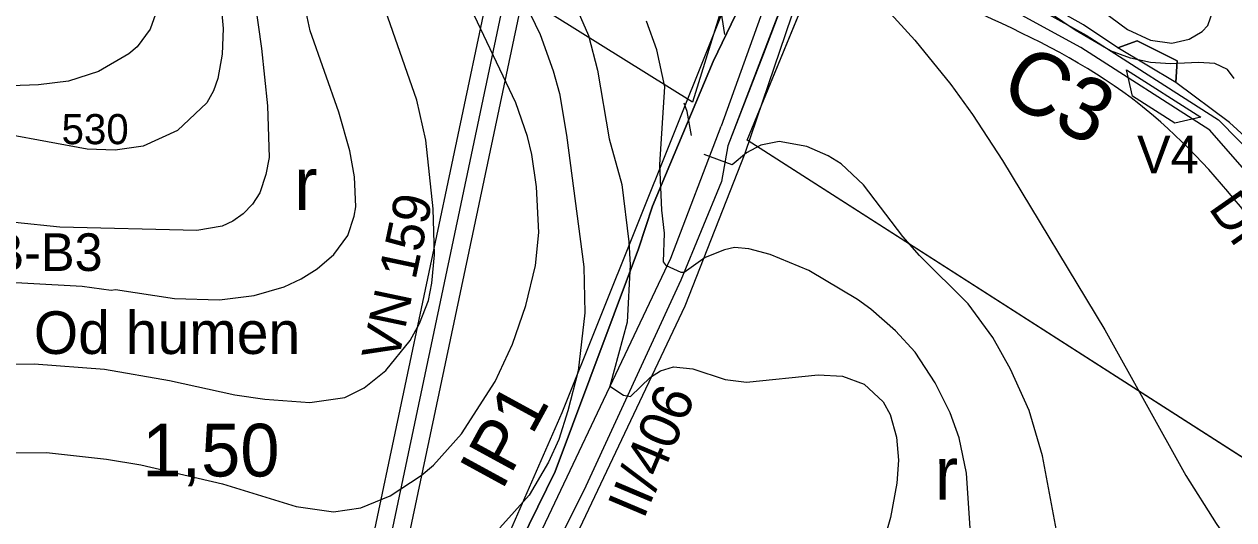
# Model space of a CAD drawing. Extents: x -684583 to -680383, y -1157874 to -1154904.
# Drawn here: x -683060.3 to -682578.4, y -1156304.8 to -1156107.3 of the extents above; entities that cross this region are included whole.
import ezdxf

# ---------------------------------------------------------------- set-up
doc = ezdxf.new("R2010")
doc.units = 0
for name, color, linetype in [('01_DOPRAVA', 7, 'Continuous'), ('01_MÍSTNÍ_NÁZVY', 7, 'Continuous'), ('01_VRSTEVNICE', 7, 'Continuous'), ('02_KULTURY STAV', 7, 'Continuous'), ('03_PC_NÁVRH', 7, 'Continuous'), ('03_PC_OBJEKTY_NÁVRH', 7, 'Continuous'), ('03_PC_POPIS_NÁVRH', 7, 'Continuous'), ('05_VHO_MELIORACE', 7, 'Continuous'), ('06_BIOGEOGRAFIE', 7, 'Continuous'), ('06_ÚSES_IP', 7, 'Continuous'), ('07_ELEKTRO', 7, 'Continuous'), ('07_OCH_P A POPISY TI', 7, 'Continuous')]:
    doc.layers.add(name, color=color, linetype=linetype)

msp = doc.modelspace()

# ---------------------------------------------------------------- linework, layer by layer
at = {"layer": '01_DOPRAVA'}
for points in [[(-682444.78, -1155001.44), (-682484.97, -1155081.41), (-682523.81, -1155212.27), (-682554.69, -1155333.36), (-682575.58, -1155465.36), (-682603.29, -1155587.36), (-682620.55, -1155650.97), (-682668.34, -1155796.22), (-682702.3, -1155906.34), (-682764.53, -1156097.63), (-682782.62, -1156147.93)], [(-683054.51, -1157758.92), (-683045.66, -1157702.14), (-683033.32, -1157625.99), (-683033.32, -1157571.3), (-683045.07, -1157508.09), (-683105.62, -1157372.25), (-683148.82, -1157294.04), (-683163.81, -1157254.05), (-683168.81, -1157196.71), (-683165.28, -1157159.67), (-683135.89, -1157075.28), (-683079.46, -1156981.49), (-683035.96, -1156902.98), (-682993.94, -1156817.72), (-682972.78, -1156716.87), (-682952.5, -1156631.31), (-682921.05, -1156497.23), (-682883.43, -1156372.57), (-682870.79, -1156344.34), (-682802.61, -1156200.56), (-682782.62, -1156147.93)]]:
    msp.add_lwpolyline(points, dxfattribs=at)
at = {"layer": '01_VRSTEVNICE'}
for points in [[(-683067.75, -1155919.88), (-683036.22, -1155954.68), (-683024.67, -1155968.38), (-683001.7, -1155998.33), (-682988.3, -1156021.15), (-682981.45, -1156037.13), (-682975.74, -1156055.39), (-682971.18, -1156078.21), (-682965.76, -1156117.01), (-682963.33, -1156139.83), (-682962.76, -1156160.37), (-682964.05, -1156167.22), (-682966.47, -1156174.5), (-682969.33, -1156179.06), (-682973.03, -1156182.91), (-682977.17, -1156185.76), (-682981.45, -1156187.76), (-682991.58, -1156189.47), (-683046.07, -1156188.19), (-683064.04, -1156186.33)], [(-683080.59, -1155932.71), (-683049.06, -1155970.51), (-683014.69, -1156013.74), (-683007.84, -1156023.44), (-683002.13, -1156033.14), (-682993.15, -1156052.53), (-682987.01, -1156073.08), (-682982.02, -1156098.75), (-682981.02, -1156109.02), (-682981.45, -1156119.29), (-682983.16, -1156128.99), (-682984.87, -1156133.84), (-682987.58, -1156138.69), (-682999.28, -1156149.68), (-683012.97, -1156155.95), (-683024.1, -1156157.52), (-683035.23, -1156157.09), (-683066.89, -1156151.24)], [(-683077.45, -1155954.68), (-683041.5, -1156006.32), (-683034.8, -1156016.87), (-683026.24, -1156032.85), (-683022.96, -1156040.84), (-683021.39, -1156047.54), (-683010.41, -1156079.07), (-683007.41, -1156092.76), (-683007.98, -1156103.32), (-683010.12, -1156109.31), (-683015.26, -1156116.3), (-683018.68, -1156119.15), (-683030.66, -1156126.14), (-683042.65, -1156129.99), (-683054.63, -1156131.42), (-683087.43, -1156132.7)], [(-682860.35, -1155997.05), (-682824.68, -1156034.56), (-682803, -1156061.09), (-682796.3, -1156070.51), (-682791.31, -1156079.07), (-682786.17, -1156090.48), (-682783.03, -1156100.46), (-682781.32, -1156111.45)], [(-682881.82, -1156065.53), (-682873.04, -1156078.5), (-682860.77, -1156099.04), (-682854.78, -1156111.45), (-682849.5, -1156125.85), (-682847.08, -1156134.98), (-682844.23, -1156151.53), (-682837.38, -1156204.02), (-682836.95, -1156222.28), (-682839.66, -1156245.39), (-682843.66, -1156261.37), (-682847.36, -1156272.78), (-682851.36, -1156281.91), (-682859.06, -1156295.03), (-682870.76, -1156308.01)], [(-683082.01, -1156243.11), (-683056.34, -1156242.68), (-683028.38, -1156244.82), (-683002.42, -1156249.24), (-682976.46, -1156254.95), (-682964.48, -1156256.8), (-682946.5, -1156258.08), (-682932.52, -1156256.09), (-682924.82, -1156252.24), (-682916.26, -1156245.25), (-682906.56, -1156233.41), (-682902.85, -1156226.56), (-682899.29, -1156217.43), (-682897.86, -1156210.58), (-682896.86, -1156199.17), (-682897.43, -1156180.91), (-682900.29, -1156153.53), (-682903.85, -1156137.55), (-682922.97, -1156082.78)], [(-682578.2, -1156128.99), (-682580.91, -1156125.43), (-682585.9, -1156123), (-682592.46, -1156122.57), (-682603.59, -1156123.14), (-682611.58, -1156122.57), (-682619.56, -1156120.86), (-682627.55, -1156117.87), (-682641.53, -1156109.73), (-682680.9, -1156083.06)], [(-683078.31, -1156209.44), (-683037.22, -1156211.73), (-683025.67, -1156213.29), (-683023.96, -1156213.01), (-683000.42, -1156216.57), (-682982.45, -1156217.15), (-682968.75, -1156215.43), (-682956.77, -1156212.01), (-682949.93, -1156208.73), (-682943.65, -1156204.74), (-682936.95, -1156199.03), (-682931.38, -1156191.47), (-682928.81, -1156183.77), (-682928.24, -1156180.06), (-682928.67, -1156168.08), (-682930.53, -1156157.81), (-682934.95, -1156142.4), (-682946.36, -1156110.02), (-682949.93, -1156093.05)], [(-682745.52, -1156093.9), (-682737.96, -1156090.76), (-682731.82, -1156090.48), (-682727.69, -1156091.9), (-682722.12, -1156095.33), (-682705.43, -1156113.73), (-682691.17, -1156131.28), (-682682.47, -1156143.26), (-682670.49, -1156161.66), (-682629.69, -1156229.13), (-682597.45, -1156287.18), (-682585.33, -1156306.3), (-682572.83, -1156324.37)], [(-682841.52, -1156098.18), (-682835.53, -1156111.88), (-682831.96, -1156125.57), (-682827.25, -1156152.96), (-682822.26, -1156171.21), (-682819.41, -1156194.04), (-682818.84, -1156203.17), (-682820.12, -1156225.99), (-682826.97, -1156251.52), (-682821.55, -1156255.09), (-682818.69, -1156255.66), (-682810.71, -1156247.96), (-682806.85, -1156245.39), (-682801.58, -1156243.82), (-682793.87, -1156244.68), (-682781.04, -1156248.96), (-682772.48, -1156249.95), (-682743.95, -1156247.1), (-682734.25, -1156247.53), (-682725.69, -1156250.81), (-682718.13, -1156257.8), (-682715.28, -1156262.79), (-682712.71, -1156271.92), (-682712, -1156281.05), (-682712.57, -1156290.18), (-682715.13, -1156303.87), (-682721.7, -1156326.7)], [(-682637.11, -1156097.18), (-682620.7, -1156109.45), (-682611.58, -1156113.73), (-682603.02, -1156114.87), (-682596.17, -1156113.3), (-682591.03, -1156110.16), (-682588.75, -1156107.88), (-682586.75, -1156102.17)], [(-683087.72, -1156278.2), (-683051.49, -1156278.05), (-683027.52, -1156280.62), (-683013.83, -1156282.9), (-682981.31, -1156290.46), (-682951.92, -1156299.45), (-682937.09, -1156301.59), (-682926.25, -1156300.02), (-682914.55, -1156295.31), (-682902.14, -1156287.18), (-682897.29, -1156283.05), (-682886.02, -1156270.49), (-682872.61, -1156249.67), (-682865.77, -1156234.83), (-682860.49, -1156219.43), (-682856.64, -1156203.45), (-682855.21, -1156190.33), (-682856.21, -1156172.07), (-682858.06, -1156159.23), (-682859.78, -1156152.1), (-682864.48, -1156138.69), (-682881.03, -1156103.74)], [(-682683.18, -1156312.15), (-682684.89, -1156286.19), (-682687.75, -1156272.21), (-682691.31, -1156262.22), (-682697.3, -1156250.24), (-682705.29, -1156237.97), (-682713.14, -1156229.56), (-682722.98, -1156220.85), (-682728.26, -1156217), (-682747.66, -1156205.45), (-682763.06, -1156199.03), (-682771.62, -1156196.89), (-682777.33, -1156196.32), (-682781.32, -1156197.18), (-682789.02, -1156200.31), (-682797.3, -1156206.3), (-682798.58, -1156206.3), (-682804.43, -1156203.59), (-682805.57, -1156202.03), (-682805.14, -1156190.61), (-682806.28, -1156181.49), (-682807, -1156163.23), (-682805, -1156132.27), (-682808.28, -1156117.58), (-682812.42, -1156106.17)], [(-682794.44, -1156151.67), (-682796.16, -1156142.12), (-682797.3, -1156138.83)], [(-682600.59, -1156391.28), (-682610.86, -1156379.33), (-682622.13, -1156364.93), (-682631.54, -1156351.23), (-682639.25, -1156337.25), (-682643.67, -1156327.27), (-682648.23, -1156313.29), (-682654.65, -1156279.34), (-682659.93, -1156261.22), (-682667.35, -1156244.82), (-682674.34, -1156232.12), (-682684.18, -1156218.72), (-682703.58, -1156199.46), (-682710.28, -1156191.9), (-682725.97, -1156171.36), (-682734.82, -1156162.94), (-682739.95, -1156159.8), (-682748.51, -1156156.09), (-682759.5, -1156154.1), (-682766.77, -1156155.52), (-682772.48, -1156158.52), (-682778.18, -1156163.37), (-682789.45, -1156159.23)]]:
    msp.add_lwpolyline(points, dxfattribs=at)
at = {"layer": '02_KULTURY STAV'}
for points in [[(-682866.04, -1156320.76), (-682848.78, -1156285.62), (-682834.97, -1156248.66), (-682815.59, -1156196.79), (-682810.04, -1156179.89), (-682785.78, -1156122.22), (-682776.79, -1156103.44), (-682762.11, -1156061.38), (-682758.74, -1156052.65), (-682753.41, -1156039.97), (-682742.95, -1156008.33), (-682725.67, -1156001.43), (-682739.11, -1156046.65), (-682740.04, -1156050.18), (-682744.64, -1156063.3), (-682765.72, -1156119.15), (-682779.93, -1156155.81), (-682782.44, -1156169.94), (-682798.74, -1156209.36), (-682837.34, -1156293.13), (-682860.97, -1156340.11)], [(-682569.3, -1156156.35), (-682580.04, -1156146.44), (-682601.47, -1156130.49), (-682600.97, -1156121.96), (-682616.85, -1156113.92), (-682624.62, -1156116.74), (-682638.27, -1156107.54), (-682659.05, -1156095.72), (-682693.74, -1156078.06), (-682714.33, -1156069.98), (-682731.17, -1156065.1), (-682744.64, -1156063.3), (-682742.82, -1156058.77), (-682735.27, -1156055.51), (-682726.38, -1156048.39), (-682702.07, -1156019.82), (-682695.09, -1156023.72), (-682560.35, -1156103.1)], [(-682596.72, -1156380.07), (-682557.32, -1156288.22), (-682537.57, -1156239.43), (-682529.35, -1156221.47), (-682529.35, -1156221.47), (-682525.25, -1156214.91), (-682536.68, -1156197.77), (-682569.3, -1156156.35), (-682580.04, -1156146.44), (-682601.47, -1156130.49), (-682624.62, -1156116.74), (-682638.27, -1156107.54), (-682659.05, -1156095.72), (-682693.74, -1156078.06), (-682714.33, -1156069.98), (-682731.17, -1156065.1), (-682740.76, -1156063.41), (-682744.64, -1156063.3), (-682779.93, -1156155.81), (-682782.44, -1156169.94), (-682798.74, -1156209.36), (-682837.34, -1156293.13), (-682860.97, -1156340.11)], [(-682776.79, -1156103.44), (-682785.78, -1156122.22), (-682810.04, -1156179.89), (-682815.59, -1156196.79), (-682834.97, -1156248.66), (-682848.78, -1156285.62), (-682866.04, -1156320.76)]]:
    msp.add_lwpolyline(points, dxfattribs=at)
msp.add_lwpolyline([(-682624.62, -1156116.74), (-682616.85, -1156113.92), (-682600.97, -1156121.96), (-682601.47, -1156130.49)], close=True, dxfattribs=at)
at = {"layer": '03_PC_NÁVRH'}
msp.add_lwpolyline([(-682748.06, -1156060.15), (-682693.66, -1156080.3), (-682637.14, -1156111.72), (-682584.4, -1156145.39), (-682568.41, -1156161.75), (-682527.4, -1156217.35)], dxfattribs=at)
at = {"layer": '03_PC_OBJEKTY_NÁVRH'}
msp.add_lwpolyline([(-682540.56, -1156208.64), (-682574.04, -1156165.3), (-682587.85, -1156149.61), (-682639.37, -1156116.57), (-682695.33, -1156085.89), (-682737, -1156069.49)], dxfattribs=at)
msp.add_lwpolyline([(-682591.44, -1156144.41), (-682601.8, -1156146.7), (-682618.66, -1156135.94), (-682621.16, -1156125.44)], close=True, dxfattribs=at)
at = {"layer": '05_VHO_MELIORACE'}
for p, q in [((-682772.31, -1156153.49), (-682747.8, -1156093.97)), ((-682567.04, -1156285.02), (-682772.31, -1156153.49))]:
    msp.add_line(p, q, dxfattribs=at)
msp.add_lwpolyline([(-682427.32, -1155652.04), (-682442.64, -1155733.79), (-682379.89, -1155766.86), (-682399.94, -1155848.22), (-682465.23, -1155827.02), (-682513.91, -1155819), (-682556.29, -1155928.43), (-682568.9, -1156017.02), (-682570.04, -1156062.28), (-682551.72, -1156093.79), (-682504.18, -1156161.97), (-682541.38, -1156231.07), (-682567.04, -1156285.02), (-682772.31, -1156153.49), (-682747.8, -1156093.97), (-682704.39, -1155977.74), (-682664.8, -1155838.52), (-682635.04, -1155749.47), (-682580.41, -1155551.03)], dxfattribs=at)
msp.add_lwpolyline([(-683016.49, -1155781.73), (-682936.04, -1155794.17), (-682848.83, -1155761.96), (-682691.86, -1155808.93), (-682793.99, -1156138.37), (-682858.18, -1156098.46), (-682817.93, -1155910.57), (-682879.64, -1155866.28), (-683019.17, -1155809.91)], close=True, dxfattribs=at)
at = {"layer": '06_BIOGEOGRAFIE'}
for points in [[(-682624.87, -1154935.44), (-682669.05, -1155140.04), (-682739.65, -1155253.72), (-682834.36, -1155382.91), (-682941.12, -1155661.96), (-683008.28, -1155760.14), (-683056.49, -1155810.09), (-683084.04, -1155808.37), (-683154.45, -1155886.49), (-683231.94, -1156062.19), (-683280.08, -1156211.64), (-683362.74, -1156430.39), (-683497.05, -1156731.83), (-683541.82, -1156781.78), (-683638.25, -1156792.12), (-683701.96, -1156768), (-683817.33, -1156693.94)], [(-682538.3, -1156231.46), (-682619.23, -1156136.72), (-682741.49, -1156072.99), (-682905.07, -1155940.36), (-683017, -1155857.68), (-683037.66, -1155826.67), (-683017, -1155811.17), (-682820.7, -1155868.01), (-682758.71, -1155893.85), (-682674.33, -1155943.8), (-682548.63, -1156054.04), (-682459.09, -1156176.34)]]:
    msp.add_spline(points, degree=3, dxfattribs=at)
at = {"layer": '06_ÚSES_IP'}
for points in [[(-682530.18, -1155187.74), (-682556.31, -1155287.32), (-682580.65, -1155417.4), (-682596.62, -1155505.37), (-682619.02, -1155596.96), (-682637.3, -1155662.36), (-682672.55, -1155772.07), (-682712.43, -1155905.02), (-682772.45, -1156078.06), (-682846.1, -1156262.2), (-682899.06, -1156383.28), (-682928.82, -1156472.07), (-682968.71, -1156622.54), (-683017.6, -1156838.34)], [(-683045.5, -1156945.1), (-682993.87, -1156850.83), (-682970.35, -1156763.63), (-682943.14, -1156635.49), (-682907.69, -1156485.87), (-682877.43, -1156403.71), (-682855.81, -1156343.74), (-682797.01, -1156219.49), (-682773.09, -1156158.67), (-682722.07, -1156008.47), (-682663.84, -1155833.77), (-682598.99, -1155629.09), (-682554.6, -1155429.31), (-682533.56, -1155299)]]:
    msp.add_lwpolyline(points, dxfattribs=at)
at = {"layer": '07_ELEKTRO'}
msp.add_lwpolyline([(-683353.35, -1157770.3), (-683109.07, -1157109.08), (-683073.5, -1157019.42), (-683054.68, -1156978.22), (-683011.49, -1156911.63), (-683020.57, -1156816.29), (-682818.44, -1155857.57), (-682314.17, -1155533.82)], dxfattribs=at)
msp.add_lwpolyline([(-683353.35, -1157770.3), (-683109.07, -1157109.08), (-683073.5, -1157019.42), (-683054.68, -1156978.22), (-683011.49, -1156911.63), (-683020.57, -1156816.29), (-682818.44, -1155857.57), (-682314.17, -1155533.82)], dxfattribs=at)
at = {"layer": '07_OCH_P A POPISY TI'}
for p, q in [((-683013.5, -1156816.69), (-682812.19, -1155861.88)), ((-682826.85, -1155863.53), (-683027.64, -1156815.89))]:
    msp.add_line(p, q, dxfattribs=at)

# ---------------------------------------------------------------- texts
at = {"layer": '01_DOPRAVA'}
msp.add_text('II/406', height=16, rotation=67.0787, dxfattribs=at).set_placement((-682813.55, -1156305))
at = {"layer": '01_MÍSTNÍ_NÁZVY'}
msp.add_text('Od humen', height=17, dxfattribs=at).set_placement((-683056.5, -1156238.73))
at = {"layer": '01_VRSTEVNICE'}
msp.add_text('530', height=12, dxfattribs=at).set_placement((-683045.44, -1156155.13))
at = {"layer": '02_KULTURY STAV'}
for p in [(-682952.77, -1156181.38), (-682697.55, -1156296.73)]:
    msp.add_text('r', height=21, dxfattribs=at).set_placement(p)
at = {"layer": '03_PC_OBJEKTY_NÁVRH'}
msp.add_text('V4', height=15, dxfattribs=at).set_placement((-682616.9, -1156166.73))
msp.add_text('DR3', height=15, rotation=304.992, dxfattribs=at).set_placement((-682588.72, -1156180.62))
at = {"layer": '03_PC_POPIS_NÁVRH'}
msp.add_text('C3', height=25, rotation=332.4682, dxfattribs=at).set_placement((-682672.68, -1156136.52))
at = {"layer": '06_BIOGEOGRAFIE'}
for s, height, p in [('5AB-B3', 15, (-683098.22, -1156205.66)), ('1,50', 21, (-683013.26, -1156287.55))]:
    msp.add_text(s, height=height, dxfattribs=at).set_placement(p)
at = {"layer": '06_ÚSES_IP'}
msp.add_text('IP1', height=20, rotation=61.4024, dxfattribs=at).set_placement((-682870.02, -1156293.58))
at = {"layer": '07_OCH_P A POPISY TI'}
msp.add_text('VN 159', height=15, rotation=78.0945, dxfattribs=at).set_placement((-682911.33, -1156242.25))

doc.saveas('drawing.dxf')
